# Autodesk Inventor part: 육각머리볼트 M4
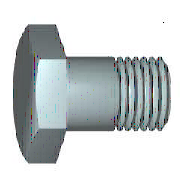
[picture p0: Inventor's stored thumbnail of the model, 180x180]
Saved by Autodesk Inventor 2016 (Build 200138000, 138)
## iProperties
IsCustomPart: 1
Created: 2012-02
Part Number: 육각머리볼트 M4
Material: 스테인리스강
Description: 6각 머리 볼트 및 6각 머리 나사
Document SubType Name: Modeling
Standard: KS B 1002
Designer: mduedu
Standards Organization: KS
Language: ko-KR
Size Designation: A + B M4 x 10
Categories: <MemberInstance><Categories><Category DisplayName="조임쇠" InternalName="e4da775c-781d-43d5-af7c-5136215cf5a6" Mnemonic="FSTN"><Category DisplayName="볼트" InternalN
Density: 8.08 g/cm^3
Mass: 1.91435 g
Surface Area: 2.70732 cm^2
Volume: 0.236925 cm^3
Appearance: 반광택
Author: mduedu
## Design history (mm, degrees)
sketch "스케치1"
  geometry: L1 (0, 2.94)-(0, 2); L2 (2.1, 2)-(10, 2); L3 (10, 2)-(10, 0); L4 (10, 0)-(-0.4, 0); L5 (-2.48, 0)-(12.08, 0) reference; L6 (-0.4, 0)-(-0.4, 2.94); L7 (-0.4, 2.94)-(0, 2.94); L8 (2.1, 2)-(1.67, 2); L9 (1.67, 2)-(0, 2); L10 (0, -0.588)-(0, 3.528) reference
  constraints: 16 end point, 2 collinear, 2 perpendicular, 1 parallel
  dimensions: "d0" = 10 distance between parallel lines of L3 L1 (= NLG); "d1" = 7.9 distance from line of L2.start L3 (= GEL); "d2" = 4 diameter of L2 L4 (= GD); "d9" = 0.4001 distance between parallel lines of L6 L1 (computed from SD); "d10" = 5.88 diameter of L7 L4 (= SD2); "d13" = 0.42952 distance of L2.start L8.end (computed from GAL); "d14" = 4 diameter of L9 L4 (= BDM)
revolve "본체" sketch "스케치1" stored, may be unused: angle "d12" = 90 deg
sketch "스케치2"
  geometry: L1 (0, 4.041)-(3.5, 2.021); L2 (3.5, 2.021)-(3.5, -2.021); L3 (3.5, -2.021)-(0, -4.041); L4 (0, -4.041)-(-3.5, -2.021); L5 (-3.5, -2.021)-(-3.5, 2.021); L6 (-3.5, 2.021)-(0, 4.041); 2 further points
  constraints: 12 end point, 1 coincident, 1 vertical, 11 other
  dimensions: "d11" = 7 distance between parallel lines of L5 L2 (= SW)
extrude "머리" join sketch "스케치2" distance "d3" = 2.4 (= KOH - SD); taper "d4" = 0 deg
sketch "스케치4"
  geometry: L1 (-2.8, 3.5)-(-2.8, 4.041); L2 (-2.8, 4.041)-(-2.487, 4.041); L3 (-2.487, 4.041)-(-2.8, 3.5); L4 (-3.28, 0)-(0.08, 0) reference; L5 (-0.4, 4.041)-(-2.8, 4.041) reference; L6 (-2.8, 2.021)-(-2.8, 4.041) reference
  constraints: 6 end point, 2 collinear, 1 perpendicular, 1 vertical
  dimensions: "d5" = 30 deg angle of L3 L1 (= ANG1); "d19" = 7 diameter of L1.start L4 (= SW0)
revolve "모따기1" sketch "스케치4" stored, may be unused: angle "d21" = 90 deg
workplane "Work Plane1"
body "Solid1"
feature "스레드" dims "d15" = 7.9 (= GEL), "d16" = 0
chamfer "모따기2" distance "d6" = 0.42941 (= -0.5 x SPD + 0.5 x GD); stored, may be unused: second distance "d7" = 0.42952 (computed from GUL), angle "d55" = 45 deg
other parameters: "NLG" = 10 [user parameter; used in 1 equation term], "GD" = 4 (= NND) [user parameter; used in 2 equation terms], "BDM" = 4 (= NND) [user parameter; used in 1 equation term], "KOH" = 2.8 [user parameter; used in 1 equation term], "GEL" = 7.9 [user parameter; used in 2 equation terms], "SW" = 7 [user parameter; used in 3 equation terms], "SW0" = 7 (= SW) [user parameter; used in 1 equation term], "SPD" = 3.14117 (= NND - 1.2269 x PTC) [user parameter; used in 1 equation term], "SD2" = 5.88 (= SDH) [user parameter; used in 1 equation term], "SD" = 0.4 [user parameter; used in 2 equation terms], "ANG1" = 30 deg [user parameter; used in 1 equation term], "GAL" = 0.42941 (= 0.61345 x PTC) [user parameter; used in 1 equation term], "GUL" = 0.42941 (= 0.61345 x PTC) [user parameter; used in 1 equation term], "d8" = 0, "RR" = 0.2 [user parameter], "d57" = 0, "d58" = 0, "TPU" = 14.28571 (computed from PTC) [user parameter], "GD1" = 3.14117 (= THREADDIA - 1.2269 x PTC) [user parameter], "THREADDIA" = 4 [user parameter; used in 1 equation term], "SDH" = 5.88 [user parameter; used in 1 equation term], "SDHG" = 2.1 [user parameter], "TOA" = 30 deg [user parameter], "PTC" = 0.7 [user parameter; used in 5 equation terms], "NND" = 4 [user parameter; used in 3 equation terms], "E0" = 8.085 (= 1.155 x SW) [user parameter]
